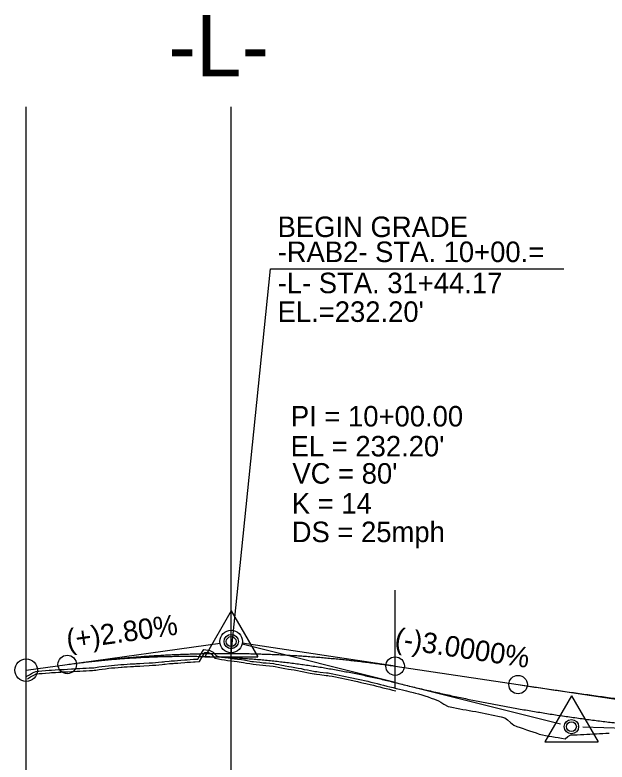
# Model space of a CAD drawing. Extents: x 2115752 to 2121174, y 562881 to 567245.
# Drawn here: x 2120069.6 to 2120214, y 564245.5 to 564427.7 of the extents above; entities that cross this region are included whole.
import ezdxf

# ---------------------------------------------------------------- set-up
doc = ezdxf.new("R2010")
doc.units = 0
for name, color, linetype in [('Exist Profile Cell', 7, 'Continuous'), ('Exist Vertical Profile Ground Line', 7, 'Continuous'), ('Prop PFL VPI Symbol CELL', 7, 'Continuous'), ('Prop Vertical Profile Curve Label', 7, 'Continuous'), ('Prop Vertical Profile Grade', 7, 'Continuous'), ('Prop Vertical Profile Grade Label', 7, 'Continuous'), ('Prop VPI Label', 7, 'Continuous'), ('Scratch_Level_1', 7, 'Continuous'), ('Scratch_Level_2', 7, 'Continuous'), ('Scratch_Level_4', 7, 'Continuous')]:
    doc.layers.add(name, color=color, linetype=linetype)

msp = doc.modelspace()

# ---------------------------------------------------------------- linework, layer by layer
at = {"layer": 'Exist Profile Cell'}
msp.add_line((2120072.308606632, 564113.9363014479), (2120072.308606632, 564363.9363014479), dxfattribs=at)
at = {"layer": 'Exist Vertical Profile Ground Line'}
for points in [[(2120072.3086, 564266.40579), (2120073.077831, 564266.85151), (2120073.847062, 564267.2973199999), (2120074.6162920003, 564267.6684849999), (2120075.0150220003, 564267.6889), (2120075.3855230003, 564267.7261699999), (2120076.1547540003, 564267.80229), (2120076.98143, 564267.8809649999), (2120077.92484, 564267.947955), (2120078.462446, 564267.9851149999), (2120079.396178, 564268.047575), (2120080.1506290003, 564268.0948200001), (2120080.770138, 564268.1198699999), (2120081.148905, 564268.13454), (2120081.539369, 564268.15105), (2120082.4015, 564268.1859299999), (2120083.343816, 564268.255405), (2120083.847062, 564268.285225), (2120084.6162920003, 564268.3296549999), (2120085.3855230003, 564268.3738849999), (2120086.1547540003, 564268.4146049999), (2120086.9239850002, 564268.4469699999), (2120087.693215, 564268.491835), (2120088.462446, 564268.53536), (2120088.838304, 564268.5559749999), (2120089.231677, 564268.61032), (2120090.000908, 564268.7287), (2120090.770139, 564268.8234600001), (2120091.539369, 564268.925805), (2120092.3854960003, 564269.0373699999), (2120093.077831, 564269.1061499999), (2120093.847062, 564269.180375), (2120094.679008, 564269.25691), (2120095.3855230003, 564269.312515), (2120095.7032270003, 564269.3370599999), (2120096.1547540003, 564269.3659900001), (2120096.9239850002, 564269.41405), (2120097.693215, 564269.4575949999), (2120098.462446, 564269.4976949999), (2120098.889126, 564269.5247099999), (2120099.231677, 564269.54577), (2120100.000908, 564269.59193), (2120100.966409, 564269.6481349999), (2120102.3086, 564269.72925), (2120103.077831, 564269.7684449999), (2120103.847062, 564269.81736), (2120104.6162920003, 564269.8959649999), (2120105.3855230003, 564269.9755099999), (2120105.820813, 564270.0228299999), (2120106.1547540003, 564270.0607100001), (2120107.2185730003, 564270.179105), (2120107.693215, 564270.21017), (2120108.148414, 564270.2392450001), (2120108.462446, 564270.262195), (2120109.231677, 564270.3172350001), (2120110.000908, 564270.3710899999), (2120110.975587, 564270.44204), (2120111.539369, 564270.48806), (2120112.3086, 564270.54991), (2120113.077831, 564270.6104199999), (2120113.506959, 564270.643425), (2120114.200075, 564270.6706999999), (2120114.6162920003, 564271.35038), (2120115.6053210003, 564272.9838599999), (2120116.1547540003, 564272.8759649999), (2120116.9239850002, 564272.8451200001), (2120117.9314880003, 564272.3746699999), (2120118.696453, 564271.429685), (2120119.332087, 564271.2887449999), (2120119.649987, 564271.231645), (2120120.000908, 564271.1815749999), (2120120.770139, 564271.07112), (2120121.539369, 564270.9599799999), (2120122.460762, 564270.8315499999), (2120123.083189, 564270.7527), (2120123.857778, 564270.653895), (2120124.794757, 564270.533445), (2120125.4069560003, 564270.438395), (2120126.181545, 564270.3163350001), (2120126.9561340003, 564270.177455), (2120127.383149, 564270.100565), (2120127.730723, 564270.0604699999), (2120128.505312, 564269.970675), (2120129.2799, 564269.8804649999), (2120130.0819, 564269.77808), (2120130.829078, 564269.730365), (2120132.6074530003, 564269.5390699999), (2120133.1812690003, 564269.443455), (2120133.927434, 564269.298765), (2120134.702023, 564269.147835), (2120135.1156800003, 564269.066855), (2120135.4766120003, 564269.0039449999), (2120136.358686, 564268.84936), (2120137.0257900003, 564268.73974), (2120137.800379, 564268.6122349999), (2120138.6132980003, 564268.4797449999), (2120139.349557, 564268.321075), (2120140.153299, 564268.1477049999), (2120140.898734, 564268.0071249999), (2120141.6733230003, 564267.86096), (2120142.676544, 564267.65766)], [(2120142.676544, 564267.65766), (2120143.222501, 564267.5923349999), (2120143.99709, 564267.4993499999), (2120145.5462680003, 564267.310615), (2120145.9844190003, 564267.276265), (2120146.320857, 564267.2147949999), (2120147.095446, 564267.0731149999), (2120147.870035, 564266.925805), (2120148.644624, 564266.76545), (2120149.419213, 564266.6049), (2120150.1996830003, 564266.443675), (2120150.96839, 564266.27465), (2120151.7429790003, 564266.104265), (2120152.868078, 564265.8574799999), (2120153.292157, 564265.7623099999), (2120154.066746, 564265.58854), (2120154.841335, 564265.414835), (2120155.259871, 564265.321025), (2120155.655931, 564265.230675), (2120156.390513, 564265.0589099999), (2120157.165102, 564264.877975), (2120157.939691, 564264.6887899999), (2120158.71428, 564264.477645), (2120159.488869, 564264.26721), (2120160.263458, 564264.077345), (2120161.0380470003, 564263.8895449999), (2120161.8126350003, 564263.70225), (2120162.587224, 564263.51679), (2120163.361813, 564263.31794), (2120164.136402, 564263.119465), (2120165.0960150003, 564262.8741749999), (2120165.6855800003, 564262.74587), (2120166.714689, 564262.5223899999), (2120167.234758, 564262.3821749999), (2120168.009347, 564262.1742349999), (2120168.783936, 564261.9672050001), (2120169.086894, 564261.8866000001), (2120169.5585250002, 564261.71215), (2120170.333114, 564261.42624), (2120171.1077030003, 564261.140955), (2120171.8822910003, 564260.85633), (2120172.850719, 564260.50152), (2120173.431469, 564260.1530549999), (2120174.206058, 564259.6896449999), (2120175.215563, 564259.087985), (2120175.7552360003, 564258.9817199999), (2120176.529825, 564258.83135), (2120177.304414, 564258.6831499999), (2120178.079003, 564258.537135), (2120178.853592, 564258.393325), (2120179.6281810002, 564258.251725), (2120180.40277, 564258.1123599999), (2120181.1773590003, 564257.9752349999), (2120181.951948, 564257.8403749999), (2120182.726536, 564257.7077899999), (2120183.501125, 564257.5742949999), (2120184.275714, 564257.3948799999), (2120185.050303, 564257.218315), (2120185.8248920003, 564257.044625), (2120186.599481, 564256.87382), (2120187.37407, 564256.7059299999), (2120188.148659, 564256.5409599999), (2120189.0846470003, 564256.345795), (2120189.6978370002, 564255.8237050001), (2120190.472426, 564255.17776), (2120191.2499100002, 564254.5431449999), (2120192.021604, 564254.2564), (2120192.796193, 564253.973525), (2120193.570781, 564253.6956199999), (2120194.34537, 564253.422715), (2120195.119959, 564253.1548449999), (2120195.8945480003, 564252.892035), (2120196.669137, 564252.6343149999), (2120197.443726, 564252.381705), (2120198.218315, 564252.1566), (2120198.992904, 564252.0177399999), (2120199.7674930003, 564251.88254), (2120200.542082, 564251.7510099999), (2120201.3166710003, 564251.623165), (2120202.09126, 564251.49902), (2120202.865849, 564251.3785900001), (2120203.7492750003, 564251.2460099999), (2120204.4150260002, 564251.7415049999), (2120205.189615, 564252.14625), (2120205.9642040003, 564252.1774149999), (2120206.738793, 564252.2104349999), (2120207.513382, 564252.245305), (2120208.3085930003, 564252.28305), (2120209.06256, 564252.3177199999), (2120209.8371490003, 564252.3552049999), (2120210.611738, 564252.3945599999), (2120211.3863270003, 564252.4357749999), (2120212.160916, 564252.4788449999), (2120212.935505, 564252.52377), (2120213.710094, 564252.570545), (2120214.4846820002, 564252.6191649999)]]:
    msp.add_lwpolyline(points, dxfattribs=at)
at = {"layer": 'Prop PFL VPI Symbol CELL'}
for p, q in [((2120122.301600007, 564282.4183000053), (2120115.8516000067, 564271.2183000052)), ((2120122.301600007, 564282.4183000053), (2120128.801600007, 564271.2183000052)), ((2120115.8516000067, 564271.2183000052), (2120128.801600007, 564271.2183000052))]:
    msp.add_line(p, q, dxfattribs=at)
for radius in [1.75, 1.2000000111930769]:
    msp.add_circle((2120122.3086, 564274.9363), radius, dxfattribs=at)
at = {"layer": 'Prop Vertical Profile Curve Label'}
for centre in [(2120162.3086, 564268.9363), (2120192.3086, 564264.4363)]:
    msp.add_circle(centre, 2.25, dxfattribs=at)
at = {"layer": 'Prop Vertical Profile Grade'}
msp.add_line((2120162.3086, 564268.9363), (2120192.3086, 564264.4363), dxfattribs=at)
for points in [[(2120122.308606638, 564272.0362999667), (2120123.9086, 564272.02366), (2120125.5086000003, 564272.00174), (2120127.1086, 564271.9705399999), (2120128.7086, 564271.9300599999), (2120130.3086, 564271.8803), (2120131.9086, 564271.82126), (2120133.5086000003, 564271.7529399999), (2120135.1086, 564271.67534), (2120136.7086, 564271.58846), (2120138.3086, 564271.4922999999), (2120139.9086, 564271.38686), (2120141.5086000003, 564271.2721399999), (2120143.1086, 564271.14814), (2120144.7086, 564271.01486), (2120146.3086, 564270.8722999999), (2120147.9086, 564270.7204600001), (2120149.5086000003, 564270.5593399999), (2120151.1086, 564270.38894), (2120152.7086, 564270.2092599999), (2120154.3086, 564270.0203), (2120155.9086, 564269.8220599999), (2120157.5086000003, 564269.61454), (2120159.1086, 564269.3977399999), (2120160.7086, 564269.17166), (2120162.3086, 564268.9363)], [(2120192.3086, 564264.4363), (2120194.3086, 564264.1376465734), (2120196.3086, 564263.8416862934), (2120198.3086, 564263.5484191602), (2120200.3086, 564263.2578451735), (2120202.3086, 564262.9699643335), (2120204.3086, 564262.6847766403), (2120206.3086, 564262.4022820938), (2120208.3086, 564262.1224806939), (2120210.3086, 564261.8453724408), (2120212.3086, 564261.5709573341), (2120214.3086, 564261.2992353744), (2120216.3086, 564261.0302065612), (2120218.3086, 564260.7638708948), (2120220.3086, 564260.5002283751), (2120222.3086, 564260.239279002), (2120224.3086, 564259.9810227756), (2120226.3086, 564259.7254596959), (2120228.3086, 564259.4725897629), (2120230.3086, 564259.2224129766), (2120232.3086, 564258.9749293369), (2120234.3086, 564258.730138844), (2120236.3086, 564258.4880414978), (2120238.3086, 564258.2486372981), (2120240.3086, 564258.0119262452), (2120242.3086, 564257.7779083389), (2120244.3086, 564257.5465835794), (2120246.3086, 564257.3179519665), (2120248.3086, 564257.0920135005), (2120250.3086, 564256.868768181), (2120252.3086, 564256.6482160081), (2120254.3086, 564256.430356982), (2120256.3086, 564256.2151911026), (2120258.3086, 564256.0027183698), (2120260.3086, 564255.7929387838), (2120262.3086, 564255.5858523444), (2120264.3086, 564255.3814590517), (2120266.3086, 564255.1797589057), (2120268.3086, 564254.9807519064), (2120270.3086, 564254.7844380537), (2120272.3086, 564254.5908173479), (2120274.3086, 564254.3998897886), (2120276.3086, 564254.211655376), (2120278.3086, 564254.02611411), (2120280.3086, 564253.8432659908), (2120282.3086, 564253.6631110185), (2120284.3086, 564253.4856491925), (2120286.3086, 564253.3108805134), (2120288.3086, 564253.1388049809), (2120290.3086, 564252.9694225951), (2120292.3086, 564252.802733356)]]:
    msp.add_spline(points, degree=3, dxfattribs=at)
at = {"layer": 'Prop VPI Label'}
for p, q in [((2120122.308606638, 564272.0362999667), (2120131.866182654, 564365.8427926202)), ((2120131.866182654, 564365.8427926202), (2120203.482517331, 564365.8427926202)), ((2120082.3086, 564269.3363), (2120119.5851601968, 564274.5550184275)), ((2120162.3086, 564268.9363), (2120125.0281749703, 564274.5283637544)), ((2120072.3086, 564267.9363), (2120082.3086, 564269.3363)), ((2120192.3086, 564264.4363), (2120239.58902503, 564257.3442362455))]:
    msp.add_line(p, q, dxfattribs=at)
for centre, radius in [((2120122.3086, 564274.9363), 2.75), ((2120082.3086, 564269.3363), 2.25)]:
    msp.add_circle(centre, radius, dxfattribs=at)
at = {"layer": 'Scratch_Level_1'}
for p, q in [((2120072.3086066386, 564113.9363014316), (2120072.3086066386, 564405.3290147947)), ((2120122.3086066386, 564113.9363014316), (2120122.3086066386, 564405.3290147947)), ((2120162.2886066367, 564263.5883372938), (2120162.2886066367, 564287.4531569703))]:
    msp.add_line(p, q, dxfattribs=at)
for points in [[(2120072.6219454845, 564265.8650131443), (2120073.3912001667, 564266.3107468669), (2120074.1399811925, 564266.7447050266), (2120074.7742605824, 564267.050754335), (2120075.0623072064, 564267.0655023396), (2120075.4475741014, 564267.1042576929), (2120076.215134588, 564267.1802123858), (2120077.0331787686, 564267.2580658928), (2120077.9685233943, 564267.3244831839), (2120078.5048524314, 564267.3615549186), (2120079.4365666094, 564267.4238799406), (2120080.182789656, 564267.4706096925), (2120080.794858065, 564267.4953588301), (2120081.174201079, 564267.5100511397), (2120081.5652034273, 564267.5265839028), (2120082.4371201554, 564267.5618598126), (2120083.3852806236, 564267.6317657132), (2120083.883566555, 564267.6612918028), (2120084.652250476, 564267.7056902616), (2120085.419981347, 564267.7498340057), (2120086.1844108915, 564267.7902998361), (2120086.9553192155, 564267.8227354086), (2120087.729064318, 564267.8678637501), (2120088.497214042, 564267.9113275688), (2120088.898286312, 564267.933325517), (2120089.3219807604, 564267.9918594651), (2120090.0866671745, 564268.1095400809), (2120090.849562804, 564268.2035196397), (2120091.6214342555, 564268.3062160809), (2120092.4572584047, 564268.4164226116), (2120093.1387388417, 564268.4841242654), (2120093.905704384, 564268.5581306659), (2120094.7321568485, 564268.6341602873), (2120095.4341131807, 564268.6894065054), (2120095.7472814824, 564268.7136010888), (2120096.194221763, 564268.7422372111), (2120096.961133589, 564268.7901523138), (2120097.7271455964, 564268.8335151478), (2120098.498461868, 564268.873723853), (2120098.928048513, 564268.9009228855), (2120099.269572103, 564268.9219197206), (2120100.037787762, 564268.9680187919), (2120101.0034214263, 564269.0242315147), (2120102.34335458, 564269.1052100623), (2120103.113566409, 564269.144455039), (2120103.8986804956, 564269.1943800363), (2120104.680203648, 564269.2742412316), (2120105.4514398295, 564269.3539935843), (2120105.889808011, 564269.4016482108), (2120106.2245415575, 564269.439618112), (2120107.2735761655, 564269.5563677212), (2120107.7335440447, 564269.5864723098), (2120108.1911119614, 564269.61569862), (2120108.507526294, 564269.6388227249), (2120109.275805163, 564269.6937945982), (2120110.0454210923, 564269.7476765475), (2120111.023699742, 564269.8188885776), (2120111.589838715, 564269.8651009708), (2120112.3581522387, 564269.9268772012), (2120113.1263016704, 564269.9873021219), (2120113.5432236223, 564270.0193683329), (2120114.558562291, 564270.0593232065), (2120115.1501151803, 564271.0253257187), (2120115.9136474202, 564272.2863753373), (2120116.0815841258, 564272.2533967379), (2120116.773397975, 564272.2256560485), (2120117.536418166, 564271.8693664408), (2120118.3480255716, 564270.8667626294), (2120119.209142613, 564270.6758259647), (2120119.5505678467, 564270.6145004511), (2120119.912350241, 564270.562880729), (2120120.68103556, 564270.4525040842), (2120121.4515404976, 564270.3411798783), (2120122.378343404, 564270.211995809), (2120123.0043734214, 564270.1326893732), (2120123.7783920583, 564270.0339571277), (2120124.7069531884, 564269.9145892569), (2120125.3103679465, 564269.8209030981), (2120126.0777395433, 564269.699980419), (2120126.845604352, 564269.5623060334), (2120127.2918667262, 564269.4819502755), (2120127.658925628, 564269.4396075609), (2120128.4331761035, 564269.3498518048), (2120129.2041744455, 564269.2600598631), (2120130.02235155, 564269.1556096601), (2120130.775715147, 564269.1074996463), (2120132.5225960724, 564268.9195923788), (2120133.0703967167, 564268.8283123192), (2120133.808177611, 564268.6852480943), (2120134.582218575, 564268.5344248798), (2120135.0019711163, 564268.4522515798), (2120135.3690085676, 564268.3882774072), (2120136.254067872, 564268.2331692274), (2120136.9243613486, 564268.1230251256), (2120137.699353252, 564267.9954538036), (2120138.497120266, 564267.865433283), (2120139.217830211, 564267.7101142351), (2120140.029473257, 564267.5350399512), (2120140.7828750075, 564267.3929575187), (2120141.553305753, 564267.2475771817), (2120142.552412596, 564267.0451109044)], [(2120142.6022909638, 564267.0370864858), (2120143.1481280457, 564266.9717758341), (2120143.922051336, 564266.8788707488), (2120145.4840227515, 564266.6885771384), (2120145.9036161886, 564266.6556820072), (2120146.208463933, 564266.5999838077), (2120146.9808337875, 564266.4587097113), (2120147.7482924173, 564266.3127557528), (2120148.517849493, 564266.153442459), (2120149.2925691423, 564265.9928653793), (2120150.069348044, 564265.8324028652), (2120150.8341449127, 564265.6642376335), (2120151.608890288, 564265.4938182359), (2120152.732695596, 564265.2473170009), (2120153.1553235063, 564265.1524726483), (2120153.9299593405, 564264.9786921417), (2120154.704606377, 564264.8049741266), (2120155.122020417, 564264.7114156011), (2120155.515275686, 564264.6217054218), (2120156.248278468, 564264.4503096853), (2120157.019870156, 564264.2700748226), (2120157.7833325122, 564264.0836073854), (2120158.5501661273, 564263.8745764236), (2120159.3325198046, 564263.6620319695), (2120160.115428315, 564263.4701277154), (2120160.8909684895, 564263.282097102), (2120161.6664237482, 564263.0945923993), (2120162.436744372, 564262.9101543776)]]:
    msp.add_lwpolyline(points, dxfattribs=at)
at = {"layer": 'Scratch_Level_2'}
for p, q in [((2120122.301600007, 564282.4183000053), (2120115.8516000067, 564271.2183000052)), ((2120122.301600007, 564282.4183000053), (2120128.801600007, 564271.2183000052)), ((2120082.3086, 564269.3363), (2120119.5851601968, 564274.5550184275)), ((2120162.3086, 564264.9363), (2120124.9764918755, 564274.2693270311)), ((2120115.8516000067, 564271.2183000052), (2120128.801600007, 564271.2183000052)), ((2120072.3086, 564267.9363), (2120082.3086, 564269.3363)), ((2120162.3086, 564264.9363), (2120202.6407081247, 564254.8532729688)), ((2120205.301600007, 564261.6683000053), (2120198.8516000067, 564250.4683000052)), ((2120205.301600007, 564261.6683000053), (2120211.801600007, 564250.4683000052)), ((2120248.3086, 564252.6804133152), (2120208.0569151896, 564254.0900522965)), ((2120198.8516000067, 564250.4683000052), (2120211.801600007, 564250.4683000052))]:
    msp.add_line(p, q, dxfattribs=at)
for centre, radius in [((2120122.3086, 564274.9363), 1.75), ((2120122.3086, 564274.9363), 1.2000000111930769), ((2120205.3086, 564254.1863), 1.75), ((2120205.3086, 564254.1863), 1.2000000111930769)]:
    msp.add_circle(centre, radius, dxfattribs=at)
for points in [[(2120082.3086, 564269.3363), (2120083.9086, 564269.55406), (2120085.5086000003, 564269.75934), (2120087.1086, 564269.95214), (2120088.7086, 564270.13246), (2120090.3086, 564270.3002999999), (2120091.9086, 564270.45566), (2120093.5086000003, 564270.5985399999), (2120095.1086, 564270.72894), (2120096.7086, 564270.8468599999), (2120098.3086, 564270.9522999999), (2120099.9086, 564271.0452599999), (2120101.5086000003, 564271.1257399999), (2120103.1086, 564271.1937399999), (2120104.7086, 564271.24926), (2120106.3086, 564271.2923), (2120107.9086, 564271.3228600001), (2120109.5086000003, 564271.3409399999), (2120111.1086, 564271.3465399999), (2120112.7086, 564271.3396599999), (2120114.3086, 564271.3203), (2120115.9086, 564271.28846), (2120117.5086000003, 564271.24414), (2120119.1086, 564271.18734), (2120120.7086, 564271.11806), (2120122.3086, 564271.0362999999), (2120123.9086, 564270.9420599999), (2120125.5086000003, 564270.83534), (2120127.1086, 564270.7161399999), (2120128.7086, 564270.5844599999), (2120130.3086, 564270.4403), (2120131.9086, 564270.28366), (2120133.5086000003, 564270.11454), (2120135.1086, 564269.93294), (2120136.7086, 564269.7388599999), (2120138.3086, 564269.5323), (2120139.9086, 564269.31326), (2120141.5086000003, 564269.0817399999), (2120143.1086, 564268.83774), (2120144.7086, 564268.5812599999), (2120146.3086, 564268.3123), (2120147.9086, 564268.0308599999), (2120149.5086000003, 564267.73694), (2120151.1086, 564267.43054), (2120152.7086, 564267.1116599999), (2120154.3086, 564266.7803), (2120155.9086, 564266.43646), (2120157.5086000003, 564266.08014), (2120159.1086, 564265.7113399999), (2120160.7086, 564265.33006), (2120162.3086, 564264.9363)], [(2120122.308606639, 564271.036299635), (2120123.9086, 564270.9420599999), (2120125.5086000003, 564270.83534), (2120127.1086, 564270.7161399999), (2120128.7086, 564270.5844599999), (2120130.3086, 564270.4403), (2120131.9086, 564270.28366), (2120133.5086000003, 564270.11454), (2120135.1086, 564269.93294), (2120136.7086, 564269.7388599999), (2120138.3086, 564269.5323), (2120139.9086, 564269.31326), (2120141.5086000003, 564269.0817399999), (2120143.1086, 564268.83774), (2120144.7086, 564268.5812599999), (2120146.3086, 564268.3123), (2120147.9086, 564268.0308599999), (2120149.5086000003, 564267.73694), (2120151.1086, 564267.43054), (2120152.7086, 564267.1116599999), (2120154.3086, 564266.7803), (2120155.9086, 564266.43646), (2120157.5086000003, 564266.08014), (2120159.1086, 564265.7113399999), (2120160.7086, 564265.33006), (2120162.3086, 564264.9363)], [(2120162.3086, 564264.9363), (2120164.0286000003, 564264.5099976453), (2120165.7486, 564264.0910905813), (2120167.4686000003, 564263.679578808), (2120169.1886, 564263.2754623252), (2120170.9086, 564262.8787411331), (2120172.6286, 564262.4894152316), (2120174.3486, 564262.107484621), (2120176.0686, 564261.7329493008), (2120177.7886, 564261.3658092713), (2120179.5086000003, 564261.0060645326), (2120181.2286, 564260.6537150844), (2120182.9486000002, 564260.308760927), (2120184.6686, 564259.97120206), (2120186.3886, 564259.6410384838), (2120188.1086, 564259.3182701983), (2120189.8286, 564259.0028972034), (2120191.5486000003, 564258.6949194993), (2120193.2686, 564258.3943370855), (2120194.9886000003, 564258.1011499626), (2120196.7086, 564257.8153581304), (2120198.4286, 564257.5369615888), (2120200.1486, 564257.2659603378), (2120201.8686, 564257.0023543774), (2120203.5886, 564256.7461437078), (2120205.3086, 564256.4973283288), (2120207.0286000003, 564256.2559082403), (2120208.7486, 564256.0218834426), (2120210.4686000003, 564255.7952539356), (2120212.1886, 564255.5760197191), (2120213.9086, 564255.3641807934), (2120215.6286, 564255.1597371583), (2120217.3486, 564254.9626888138), (2120219.0686, 564254.77303576), (2120220.7886, 564254.5907779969), (2120222.5086000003, 564254.4159155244), (2120224.2286, 564254.2484483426), (2120225.9486000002, 564254.0883764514), (2120227.6686, 564253.9356998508), (2120229.3886, 564253.790418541), (2120231.1086, 564253.6525325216), (2120232.8286, 564253.5220417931), (2120234.5486000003, 564253.3989463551), (2120236.2686, 564253.2832462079), (2120237.9886000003, 564253.1749413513), (2120239.7086, 564253.0740317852), (2120241.4286, 564252.98051751), (2120243.1486, 564252.8943985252), (2120244.8686, 564252.8156748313), (2120246.5886, 564252.7443464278), (2120248.3086, 564252.6804133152)]]:
    msp.add_spline(points, degree=3, dxfattribs=at)
at = {"layer": 'Scratch_Level_4'}
msp.add_circle((2120072.3086, 564267.9363), 2.75, dxfattribs=at)
msp.add_spline([(2120082.3086, 564269.3363), (2120083.9086, 564269.55566), (2120085.5086000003, 564269.76574), (2120087.1086, 564269.9665399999), (2120088.7086, 564270.1580599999), (2120090.3086, 564270.3402999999), (2120091.9086, 564270.5132599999), (2120093.5086000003, 564270.6769399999), (2120095.1086, 564270.8313399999), (2120096.7086, 564270.9764599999), (2120098.3086, 564271.1122999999), (2120099.9086, 564271.2388599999), (2120101.5086000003, 564271.35614), (2120103.1086, 564271.46414), (2120104.7086, 564271.56286), (2120106.3086, 564271.6523), (2120107.9086, 564271.73246), (2120109.5086000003, 564271.8033400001), (2120111.1086, 564271.8649400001), (2120112.7086, 564271.9172599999), (2120114.3086, 564271.9602999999), (2120115.9086, 564271.9940599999), (2120117.5086000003, 564272.01854), (2120119.1086, 564272.03374), (2120120.7086, 564272.0396599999), (2120122.3086, 564272.0362999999), (2120122.308606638, 564272.0362999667)], degree=3, dxfattribs=at)

# ---------------------------------------------------------------- texts
at = {"layer": 'Prop Vertical Profile Curve Label'}
for s, p in [("VC = 80'", (2120137.243752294, 564313.4311725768)), ('K = 14', (2120137.092285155, 564306.1095311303)), ('DS = 25mph', (2120137.076942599, 564299.168161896))]:
    msp.add_text(s, height=5, dxfattribs=at).set_placement(p)
at = {"layer": 'Prop Vertical Profile Grade Label'}
for s, rotation, p in [('(+)2.80%', 7.969610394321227, (2120082.4539103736, 564272.8687599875)), ('(-)3.0000%', 351.46923439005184, (2120161.977376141, 564273.3763888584))]:
    msp.add_text(s, height=5, rotation=rotation, dxfattribs=at).set_placement(p)
at = {"layer": 'Prop VPI Label'}
for s, p in [('BEGIN GRADE', (2120133.637991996, 564373.5479918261)), ('-RAB2- STA. 10+00.=', (2120133.637991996, 564367.450066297)), ('-L- STA. 31+44.17', (2120133.637991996, 564359.863927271)), ("EL.=232.20'", (2120133.637991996, 564352.8658504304)), ('PI = 10+00.00', (2120136.878530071, 564327.3645930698)), ("EL = 232.20'", (2120136.8054856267, 564320.0689718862))]:
    msp.add_text(s, height=5, dxfattribs=at).set_placement(p)
at = {"layer": 'Scratch_Level_1'}
msp.add_text('-L-', height=15, dxfattribs=at).set_placement((2120107.0069259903, 564412.7045747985))

doc.saveas('drawing.dxf')
